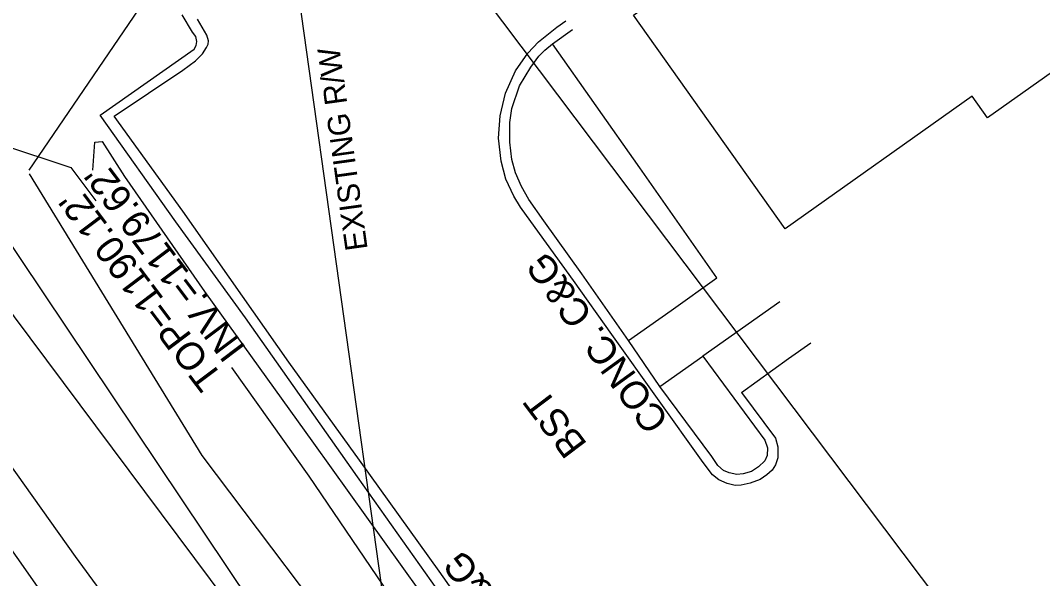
# Model space of a CAD drawing. Extents: x 1262092 to 1264624, y 774970 to 778314.
# Drawn here: x 1263536.5 to 1263683.6, y 776515.7 to 776596.1 of the extents above; entities that cross this region are included whole.
import ezdxf

# ---------------------------------------------------------------- set-up
doc = ezdxf.new("R2010")
doc.units = 0
for name, color, linetype in [('COGO Default Parcel', 7, 'Continuous'), ('Exist Right of Way Line', 7, 'Continuous'), ('Exist Right of Way Line Text', 7, 'Continuous'), ('Exist Roads Curbs', 7, 'Continuous'), ('Exist Roads EOP Other', 7, 'Continuous'), ('Exist Structure Minor Pipes RCP 24 Inch', 7, 'Continuous'), ('Exist Utilities Sanitary Sewer Manhole Leader', 7, 'Continuous'), ('Exist Utilities Sanitary Sewer Manhole Text', 7, 'Continuous'), ('Exist Utilities Sanitary Sewer UG Line', 7, 'Continuous'), ('Exist Utilities TV UG Cable SUE LOS B', 7, 'Continuous'), ('Exist Utilities Water UG Line SUE LOS B', 7, 'Continuous'), ('Prop Horizontal Alignment', 7, 'Continuous'), ('Prop Horizontal Alignment Tick Label', 7, 'Continuous'), ('Prop Shade Medium', 7, 'Continuous'), ('Prop Superelevation Label', 7, 'Continuous'), ('Sheet Clip Boundary CELL', 7, 'Continuous'), ('Sheet Plot Border Outside CELL', 7, 'Continuous')]:
    doc.layers.add(name, color=color, linetype=linetype)

msp = doc.modelspace()

# ---------------------------------------------------------------- linework, layer by layer
at = {"layer": 'COGO Default Parcel'}
msp.add_line((1263602.12, 776600.93), (1264624.2, 775243.33), dxfattribs=at)
at = {"layer": 'Exist Right of Way Line'}
msp.add_line((1263568.46, 776657.05), (1263590.4, 776500.74), dxfattribs=at)
at = {"layer": 'Exist Roads Curbs'}
for points in [[(1263599.68, 776509.65), (1263584.99, 776530.41), (1263568.89, 776553.26), (1263558.84, 776567.09), (1263547.96, 776582.47), (1263561.51, 776591.96), (1263561.77, 776592.5), (1263561.88, 776593.07), (1263561.73, 776593.8), (1263561.27, 776594.43), (1263559.79, 776596.9)], [(1263645.76, 776555.58), (1263634.68, 776547.77), (1263643.6, 776535.65), (1263644.02, 776534.55), (1263643.98, 776533.47), (1263643.62, 776532.71), (1263642.72, 776531.83), (1263641.71, 776531.17), (1263640.52, 776530.82), (1263639.57, 776530.74), (1263638.49, 776530.95), (1263637.69, 776531.32), (1263636.85, 776532.03), (1263635.99, 776533.32), (1263628.53, 776543.4), (1263623.98, 776550.04), (1263617.29, 776559.62), (1263611.83, 776567.25), (1263609.64, 776570.34), (1263608.59, 776572.17), (1263607.75, 776574.14), (1263607.23, 776576.09), (1263606.92, 776578.59), (1263606.94, 776581.38), (1263607.22, 776583.44), (1263608.34, 776586.69), (1263609.96, 776589.38), (1263611.08, 776590.96), (1263611.94, 776591.82), (1263613.07, 776592.74), (1263615.94, 776594.81)]]:
    msp.add_lwpolyline(points, dxfattribs=at)
at = {"layer": 'Exist Roads EOP Other'}
for points in [[(1263607.07, 776502.16), (1263596.74, 776516.8), (1263585.3, 776532.81), (1263575.12, 776546.92), (1263559.86, 776568.65), (1263550.01, 776582.31), (1263559.88, 776588.96), (1263561.71, 776590.27), (1263562.7, 776591.29), (1263563.28, 776592.2), (1263563.51, 776592.7), (1263563.58, 776593.16), (1263563.33, 776593.99), (1263561.96, 776596.29)], [(1263640.28, 776542.53), (1263645.14, 776535.98), (1263645.5, 776534.7), (1263645.48, 776533.12), (1263645.18, 776532.13), (1263644.68, 776531.35), (1263643.89, 776530.66), (1263642.93, 776530.02), (1263641.52, 776529.46), (1263640.21, 776529.19), (1263639.33, 776529.13), (1263638.22, 776529.43), (1263636.98, 776529.95), (1263636.09, 776530.7), (1263634.76, 776532.46), (1263621.59, 776550.87), (1263616.09, 776558.67), (1263610.59, 776566.3), (1263608.46, 776569.19), (1263607.5, 776570.78), (1263606.34, 776573.25), (1263605.66, 776575.82), (1263605.29, 776579.13), (1263605.52, 776582.37), (1263606.28, 776585.64), (1263607.76, 776588.84), (1263609.53, 776591.36), (1263611.05, 776593.01), (1263613.69, 776595.14), (1263614.99, 776596.06)]]:
    msp.add_lwpolyline(points, dxfattribs=at)
at = {"layer": 'Exist Structure Minor Pipes RCP 24 Inch'}
msp.add_line((1263502.05, 776598.37), (1263629.98, 776426.93), dxfattribs=at)
at = {"layer": 'Exist Utilities Sanitary Sewer Manhole Leader'}
msp.add_lwpolyline([(1263523.17, 776581.72), (1263543.75, 776574.93), (1263547.36, 776570.14)], dxfattribs=at)
at = {"layer": 'Exist Utilities Sanitary Sewer UG Line'}
msp.add_line((1263677.43, 776351.4), (1263523.17, 776581.72), dxfattribs=at)
at = {"layer": 'Exist Utilities TV UG Cable SUE LOS B'}
for points in [[(1263537.75, 776574.54), (1263561.39, 776609.26), (1263588.74, 776643.36), (1263599.4, 776654.43), (1263604.44, 776659.94), (1263609.55, 776668.72), (1263617.19, 776683.32), (1263624.5, 776697.44), (1263665.8, 776724.26), (1263696.26, 776747.49), (1263728.48, 776775.18)], [(1263669.01, 776365.83), (1263671.56, 776379.52), (1263645.49, 776420.66), (1263617.5, 776460.63), (1263586.67, 776501.62), (1263562.63, 776533.45), (1263537.82, 776574.01)]]:
    msp.add_lwpolyline(points, dxfattribs=at)
at = {"layer": 'Exist Utilities Water UG Line SUE LOS B'}
for points in [[(1263769.27, 776215.45), (1263763.84, 776222.23), (1263735.1, 776261.82), (1263710.78, 776293), (1263676.58, 776339.78), (1263655.95, 776370.3), (1263625.27, 776411.83), (1263600.5, 776445.06), (1263569.27, 776485), (1263544.4, 776518.91), (1263522.5, 776549.75)], [(1263947.84, 775937.63), (1263921.48, 775975.65), (1263891.78, 776015.72), (1263866.35, 776051.64), (1263834.78, 776093.68), (1263806.91, 776131.82), (1263785.84, 776159.4), (1263762.42, 776192.1), (1263728.85, 776233.86), (1263701.99, 776270.27), (1263670.29, 776315.62), (1263645.61, 776350.98), (1263620.38, 776389.35), (1263590.58, 776434.56), (1263568.12, 776469.9), (1263541.87, 776510.41), (1263521.01, 776540.13)]]:
    msp.add_lwpolyline(points, dxfattribs=at)
at = {"layer": 'Prop Horizontal Alignment Tick Label'}
msp.add_lwpolyline([(1263640.28, 776542.53), (1263647.04, 776547.44), (1263650.24, 776549.69)], dxfattribs=at)
at = {"layer": 'Prop Shade Medium'}
msp.add_lwpolyline([(1263711.59, 776607.54), (1263675.65, 776582.06), (1263673.45, 776585.17), (1263646.54, 776566.1), (1263624.74, 776596.85), (1263651.24, 776615.63), (1263649.23, 776618.47), (1263685.58, 776644.24)], close=True, dxfattribs=at)
at = {"layer": 'Prop Superelevation Label'}
msp.add_line((1263628.53, 776543.4), (1263634.68, 776547.77), dxfattribs=at)
msp.add_lwpolyline([(1263623.98, 776550.04), (1263630.15, 776554.33), (1263636.7, 776559.04), (1263625.61, 776574.88), (1263613.07, 776592.74)], dxfattribs=at)
at = {"layer": 'Sheet Clip Boundary CELL'}
for points in [[(1263546.93, 776574.52), (1263547.19, 776578.58), (1263548.24, 776578.65), (1263551.46, 776573.64), (1263563, 776557.07), (1263578.69, 776535.25), (1263593.93, 776513.92), (1263603.6, 776500.12), (1263613.72, 776486.02), (1263623.32, 776472.73), (1263629.72, 776463.9), (1263639.92, 776449.68), (1263646.7, 776439.91), (1263648.66, 776436.55)], [(1263644.88, 776435.7), (1263635.03, 776449.86), (1263624.82, 776463.85), (1263615.91, 776477.16), (1263602.54, 776495.72), (1263588.69, 776514.81), (1263578.03, 776530.49), (1263566.91, 776546.14)]]:
    msp.add_lwpolyline(points, dxfattribs=at)

# ---------------------------------------------------------------- texts
at = {"layer": 'Exist Right of Way Line Text'}
msp.add_text('EXISTING R/W', height=3.2, rotation=97.9874, dxfattribs=at).set_placement((1263586.48, 776563.18))
at = {"layer": 'Exist Utilities Sanitary Sewer Manhole Text'}
for s, p in [("INV.=1179.62'", (1263569.07, 776548.92)), ("TOP=1190.12'", (1263565.75, 776544.72))]:
    msp.add_text(s, height=4, rotation=126.9874, dxfattribs=at).set_placement(p)
at = {"layer": 'Prop Horizontal Alignment'}
msp.add_text('BST', height=4, rotation=126.9874, dxfattribs=at).set_placement((1263618.17, 776535.08))
msp.add_text('BST', height=4, rotation=126.9874, dxfattribs=at).set_placement((1263618.17, 776535.08))
at = {"layer": 'Sheet Plot Border Outside CELL'}
for rotation, p in [(125.9094, (1263629.97, 776538.53)), (126.8505, (1263618.37, 776495.87))]:
    msp.add_text('CONC. C&G', height=4, rotation=rotation, dxfattribs=at).set_placement(p)

doc.saveas('drawing.dxf')
